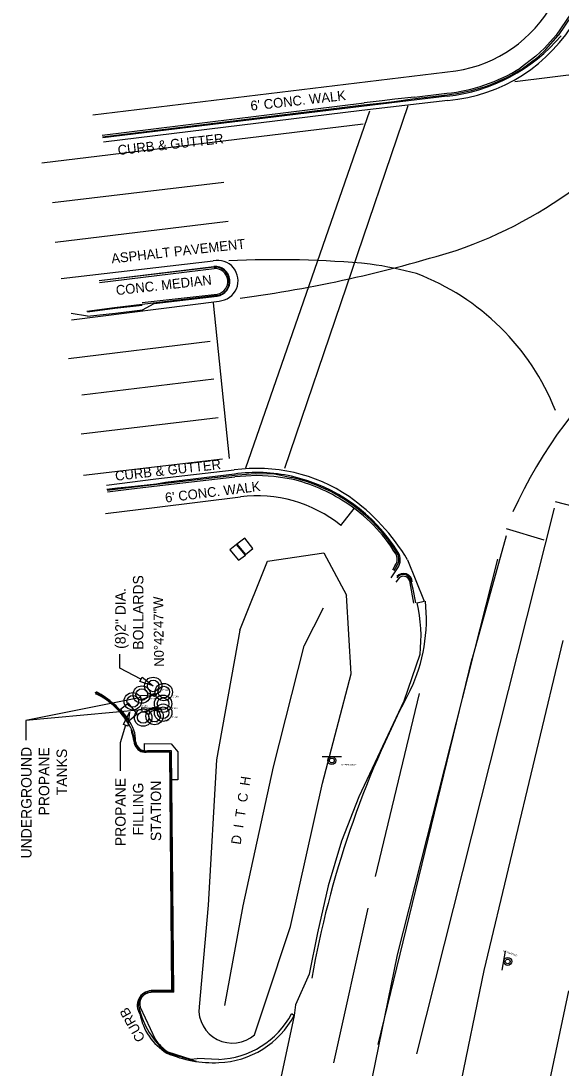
# Model space of a CAD drawing. Extents: x 925226 to 926411, y 852913 to 858733.
# Drawn here: x 925722 to 925877.3, y 857833.9 to 858134.9 of the extents above; entities that cross this region are included whole.
import ezdxf

# ---------------------------------------------------------------- set-up
doc = ezdxf.new("R2010")
doc.units = 0
for name, color, linetype in [('BankMent_ep', 7, 'Continuous'), ('CGep_ep', 7, 'Continuous'), ('CGFace_ep', 7, 'Continuous'), ('CLConst_dp', 7, 'Continuous'), ('ConcSlabs_ep', 7, 'Continuous'), ('CurbRamp_ep', 7, 'Continuous'), ('Ditch_ep', 7, 'Continuous'), ('EndTreat_ep', 7, 'Continuous'), ('LaneLine_ep', 7, 'Continuous'), ('ManholeSW_ep', 7, 'Continuous'), ('PavtAsphalt_ep', 7, 'Continuous'), ('PavtCrown_ep', 7, 'Continuous'), ('PavtMisc_ep', 7, 'Continuous'), ('Pump_ep', 7, 'Continuous'), ('SidewalkBack_ep', 7, 'Continuous'), ('TankUG_ep', 7, 'Continuous'), ('TextLabel', 7, 'Continuous'), ('TextNotes', 7, 'Continuous'), ('XSPt_ep', 7, 'Continuous')]:
    doc.layers.add(name, color=color, linetype=linetype)

# ---------------------------------------------------------------- blocks, each defined once
blk = doc.blocks.new('SSS')
at = {"layer": 'ManholeSW_ep'}
blk.add_line((-2.77, 1.15), (2.77, 1.15), dxfattribs=at)
for radius in [1.15, 0.692]:
    blk.add_circle((0, 0), radius, dxfattribs=at)
blk = doc.blocks.new('BOL')
at = {"layer": 'TextNotes'}
for radius in [2.5, 1.67]:
    blk.add_circle((0, 0), radius, dxfattribs=at)

msp = doc.modelspace()

# ---------------------------------------------------------------- linework, layer by layer
at = {"layer": 'BankMent_ep'}
msp.add_line((925879.41, 857856.06), (925859.54, 857762.3), dxfattribs=at)
at = {"layer": 'CGep_ep'}
for p, q in [((925844.57, 858113.33), (925819.92, 858110.33)), ((925819.92, 858110.33), (925745.52, 858101.32)), ((925748.99, 858052.26), (925741.1, 858051.24)), ((925756.9, 858053.15), (925748.99, 858052.26)), ((925760.95, 858001.88), (925763.57, 858002.32)), ((925763.57, 858002.32), (925783.36, 858004.67)), ((925746.74, 858000.34), (925749.79, 858000.73)), ((925749.79, 858000.73), (925752.93, 858001.01)), ((925752.93, 858001.01), (925760.95, 858001.88)), ((925828.42, 857974.82), (925830.35, 857977.68))]:
    msp.add_line(p, q, dxfattribs=at)
msp.add_arc((925839.52, 858162.39), 49.32, 275.8847, 319.9807, dxfattribs=at)
for centre, major_axis, ratio, start_param, end_param in [((925789.74, 857958.16), (5.87, -46.57), 0.999983, 2.79936, 3.152396), ((925789.14, 857956.76), (-18.57, -44.75), 0.999987, 2.514891, 3.312332), ((925827.04, 857979.96), (0.79, -3.94), 0.997503, 0.770936, 1.938401), ((925831.98, 857973.54), (-0.24, -2.54), 0.99836, 1.723789, 4.078539)]:
    msp.add_ellipse(centre, major_axis=major_axis, ratio=ratio, start_param=start_param, end_param=end_param, dxfattribs=at)
at = {"layer": 'CGFace_ep'}
for p, q in [((925880.51, 858136.71), (925876.45, 858130.76)), ((925834.59, 858112.51), (925844.5, 858113.71)), ((925745.43, 858101.64), (925820.52, 858110.81)), ((925777.48, 858064.14), (925744.52, 858060.23)), ((925778.48, 858055.96), (925756.9, 858053.41)), ((925748.88, 858052.42), (925740.96, 858051.4)), ((925756.9, 858053.41), (925748.88, 858052.42)), ((925763.54, 858002.01), (925784.24, 858004.38)), ((925746.84, 857999.99), (925752.96, 858000.75)), ((925752.96, 858000.75), (925763.54, 858002.01)), ((925830.01, 857978.15), (925829.21, 857976.86)), ((925834.75, 857971.52), (925834.11, 857974.13)), ((925835.55, 857967.58), (925834.75, 857971.52)), ((925764.94, 857924.72), (925758.33, 857924.77)), ((925765.63, 857856.07), (925764.94, 857924.72)), ((925759.41, 857855.97), (925765.63, 857856.07)), ((925764.01, 857838.27), (925772.37, 857835.86))]:
    msp.add_line(p, q, dxfattribs=at)
for centre, major_axis, ratio, start_param, end_param in [((925839.75, 858162.27), (47.08, -12.79), 0.999995, 5.075228, 5.540501), ((925777.77, 858060.02), (-4.14, -0.11), 0.998077, 1.714298, 4.755444), ((925789.06, 857956.6), (10.46, -47.15), 0.999974, 1.904479, 2.699589), ((925827.28, 857980.17), (-0.33, 3.39), 0.99614, 3.978822, 5.155955), ((925831.94, 857973.49), (1.22, -1.92), 0.991597, 1.29658, 3.544937), ((925734.57, 857922.71), (6.99, 19.88), 0.999748, 5.424017, 6.19158), ((925743.69, 857927.19), (-3.44, -10.43), 0.999738, 1.919623, 2.186463), ((925757.95, 857928.08), (3.31, -0.42), 0.999662, 3.437582, 4.951758), ((925759.49, 857852.27), (3.25, 1.78), 0.999868, 1.090636, 2.917068), ((925779.28, 857856.78), (15.79, -18.09), 0.999104, 4.226719, 4.875631)]:
    msp.add_ellipse(centre, major_axis=major_axis, ratio=ratio, start_param=start_param, end_param=end_param, dxfattribs=at)
at = {"layer": 'ConcSlabs_ep'}
for p, q in [((925784.01, 857984.35), (925782.06, 857982.85)), ((925786.53, 857981.37), (925784.01, 857984.35)), ((925786.41, 857986.2), (925784.03, 857984.49)), ((925784.03, 857984.49), (925786.57, 857981.49)), ((925788.64, 857983.23), (925786.41, 857986.2)), ((925782.06, 857982.85), (925784.56, 857979.86)), ((925784.56, 857979.86), (925786.53, 857981.37)), ((925786.57, 857981.49), (925788.64, 857983.23)), ((925757.47, 857927.2), (925757.43, 857925.08)), ((925757.47, 857927.2), (925765.19, 857927.08)), ((925765.19, 857927.08), (925767.12, 857924.82)), ((925767.12, 857924.82), (925767.08, 857916.69)), ((925767.08, 857916.69), (925765.38, 857916.73))]:
    msp.add_line(p, q, dxfattribs=at)
at = {"layer": 'CurbRamp_ep'}
for p, q in [((925875.92, 858130.82), (925872.51, 858127.09)), ((925872.95, 858126.68), (925876.45, 858130.76)), ((925872.51, 858127.09), (925870.05, 858124.81)), ((925870.63, 858124.52), (925872.95, 858126.68)), ((925870.05, 858124.81), (925865.54, 858121.38)), ((925865.78, 858121), (925870.63, 858124.52)), ((925820.52, 858110.81), (925826.01, 858111.39)), ((925825.84, 858112), (925820.67, 858111.35)), ((925829.5, 858112.43), (925825.84, 858112)), ((925826.01, 858111.39), (925829.3, 858111.72)), ((925829.3, 858111.72), (925834.59, 858112.51)), ((925835.18, 858113.03), (925829.5, 858112.43)), ((925789.82, 858004.19), (925783.52, 858003.82)), ((925784.24, 858004.38), (925789.48, 858004.83)), ((925789.48, 858004.83), (925794.91, 858004.71)), ((925794.75, 858003.98), (925789.82, 858004.19)), ((925799.75, 858003.2), (925794.75, 858003.98)), ((925794.91, 858004.71), (925799.78, 858003.7))]:
    msp.add_line(p, q, dxfattribs=at)
at = {"layer": 'Ditch_ep'}
for p, q in [((925792.92, 857979.63), (925809.04, 857981.97)), ((925809.04, 857981.97), (925815.6, 857969.8)), ((925784.94, 857959.72), (925792.92, 857979.63)), ((925816.92, 857947.18), (925815.6, 857969.8)), ((925803.41, 857955.25), (925808.97, 857966.18)), ((925784.94, 857959.72), (925778.2, 857922.52)), ((925794.64, 857920.45), (925803.41, 857955.25)), ((925808.67, 857915.73), (925816.92, 857947.18)), ((925778.2, 857922.52), (925775.84, 857880.67)), ((925785.86, 857880.51), (925794.64, 857920.45)), ((925799.52, 857874.53), (925808.67, 857915.73)), ((925775.84, 857880.67), (925773.21, 857851.51)), ((925780.67, 857851.9), (925785.86, 857880.51)), ((925792.2, 857852.6), (925799.52, 857874.53)), ((925789.15, 857843.46), (925792.2, 857852.6))]:
    msp.add_line(p, q, dxfattribs=at)
msp.add_ellipse((925782.78, 857850.66), major_axis=(-2.33, -9.33), ratio=0.999986, start_param=4.869605, end_param=7.251591, dxfattribs=at)
at = {"layer": 'EndTreat_ep'}
for p, q in [((926001.53, 858134.57), (925864.02, 858117.45)), ((925822.21, 858109.02), (925786.59, 858006.39)), ((925797.92, 858006.37), (925833.36, 858110.63)), ((925728.02, 858094.12), (925820.37, 858105.31)), ((925733.57, 858060.84), (925777.3, 858065.94)), ((925736.59, 858048.97), (925779, 858054.4)), ((925782.01, 858009.08), (925777.35, 858053.88)), ((925735.7, 858037.88), (925776.43, 858042.9)), ((925777.51, 858031.89), (925739.55, 858027.32)), ((925778.71, 858020.81), (925739.29, 858016.14)), ((925740.04, 858004.31), (925779.95, 858009.04)), ((925875.55, 857996.8), (925888.4, 857993.38)), ((925875.26, 857994.8), (925835.75, 857837.98)), ((925861.46, 857989.01), (925872.33, 857985.72)), ((925861.51, 857986.85), (925851.69, 857951.6)), ((925824.68, 857840.65), (925851.69, 857951.6)), ((925836.52, 857941.56), (925823.88, 857888.97)), ((925821.76, 857879.82), (925811.89, 857835.38))]:
    msp.add_line(p, q, dxfattribs=at)
for centre, major_axis, ratio, start_param, end_param in [((925807.98, 858185.37), (-64.65, -104.4), 0.999977, 0.878674, 1.553582), ((925735.62, 858426.35), (348.82, 136.69), 0.999242, 4.47159, 4.641363), ((925778.58, 858060.23), (-4.43, 3.83), 0.999929, 2.354299, 5.646891), ((925795.54, 857785.19), (-281.35, -14.6), 0.997761, 4.565072, 4.709651), ((925986.75, 857938.13), (-47.22, 126.76), 0.999982, 6.209163, 7.073626), ((925805.61, 857948.97), (94.25, -69.77), 0.999905, 1.947991, 2.064033), ((925811.17, 857997.43), (67.76, -14.77), 0.999977, 0.591396, 1.423059), ((925791.11, 857962.96), (31.61, -35.42), 0.999993, 0.396364, 0.951681), ((926084.23, 857810.7), (107.56, 262.01), 0.998689, 1.475772, 1.785976)]:
    msp.add_ellipse(centre, major_axis=major_axis, ratio=ratio, start_param=start_param, end_param=end_param, dxfattribs=at)
at = {"layer": 'LaneLine_ep'}
for p, q in [((925780.37, 858088.43), (925731.1, 858082.59)), ((925731.88, 858071.34), (925781.61, 858077.4))]:
    msp.add_line(p, q, dxfattribs=at)
at = {"layer": 'PavtAsphalt_ep'}
for p, q in [((925844.73, 858112.06), (925820, 858109.15)), ((925820, 858109.15), (925745.78, 858100.04)), ((925744.47, 858060.34), (925777.51, 858064.36)), ((925756.98, 858051.88), (925760.34, 858053.64)), ((925760.34, 858053.64), (925778.44, 858055.79)), ((925741.18, 858050.01), (925736.45, 858050.85)), ((925741.18, 858050.01), (925749.19, 858050.91)), ((925749.19, 858050.91), (925756.98, 858051.88)), ((925760.78, 858003.24), (925783.31, 858005.82)), ((925746.57, 858001.48), (925760.78, 858003.24)), ((925833.15, 857980.03), (925837.92, 857968.08)), ((925835.9, 857967.66), (925837.92, 857968.08)), ((925877.79, 857956.76), (925855.06, 857861.93)), ((925836.73, 857952.8), (925832.05, 857939.32)), ((925832.05, 857939.32), (925819.14, 857911.81)), ((925819.14, 857911.81), (925814.12, 857899.08)), ((925814.12, 857899.08), (925810.33, 857886.22)), ((925810.33, 857886.22), (925807.24, 857872.73)), ((925807.24, 857872.73), (925804.87, 857860.9)), ((925804.87, 857860.9), (925800.95, 857852.04)), ((925855.06, 857861.93), (925834.79, 857763.94)), ((925800.95, 857852.04), (925800.58, 857848.96)), ((925800.58, 857848.96), (925785.83, 857779.96))]:
    msp.add_line(p, q, dxfattribs=at)
for centre, major_axis, ratio, start_param, end_param in [((925840.63, 858159.33), (46.88, 7.33), 0.999985, 4.643805, 5.609384), ((925777.77, 858060.05), (-3.4, 2.67), 0.999377, 2.39093, 5.438202), ((925789.86, 857958.86), (13.96, -45.32), 0.999977, 2.250552, 2.981182), ((925781.21, 857948.82), (-44.99, -40.59), 0.999989, 2.94858, 3.360245), ((925793.57, 857957.84), (-4.64, 43.29), 0.998142, 4.489881, 4.833395)]:
    msp.add_ellipse(centre, major_axis=major_axis, ratio=ratio, start_param=start_param, end_param=end_param, dxfattribs=at)
at = {"layer": 'PavtCrown_ep'}
for p, q in [((925859.01, 857980.15), (925830.19, 857866.43)), ((925830.19, 857866.43), (925809.98, 857767.73))]:
    msp.add_line(p, q, dxfattribs=at)
at = {"layer": 'PavtMisc_ep'}
for p, q in [((925764.8, 857924.56), (925758.02, 857924.68)), ((925765.42, 857856.17), (925764.8, 857924.56)), ((925765.42, 857856.17), (925759.49, 857856.12))]:
    msp.add_line(p, q, dxfattribs=at)
for centre, major_axis, ratio, start_param, end_param in [((925733.99, 857921.6), (2.98, -21.85), 0.999501, 1.912317, 2.560267), ((925845.8, 857950.94), (61.1, -71.86), 0.99851, 4.213761, 4.268858), ((925757.74, 857927.87), (2.74, -1.68), 0.9938, 4.076968, 5.34781), ((925759.66, 857851.91), (4.13, -0.83), 0.999966, 1.81118, 3.951922), ((925772.57, 857852.38), (-11.25, 12.24), 0.998205, 1.002975, 1.852635), ((925778.04, 857860.99), (-19.75, -16.22), 0.999425, 0.916392, 1.963788), ((925777.25, 857868.34), (-32.64, -5.03), 0.997233, 1.003913, 1.467759)]:
    msp.add_ellipse(centre, major_axis=major_axis, ratio=ratio, start_param=start_param, end_param=end_param, dxfattribs=at)
at = {"layer": 'Pump_ep'}
msp.add_lwpolyline([(925753.13, 857933.82), (925755.46, 857935.71), (925752.94, 857938.82), (925750.61, 857936.93)], close=True, dxfattribs=at)
at = {"layer": 'SidewalkBack_ep'}
for p, q in [((925742.7, 858107.92), (925847.07, 858120.56)), ((925761.15, 857995.14), (925785.1, 857998.09)), ((925746.29, 857993.27), (925761.15, 857995.14)), ((925813.97, 857989.88), (925817.82, 857994.78))]:
    msp.add_line(p, q, dxfattribs=at)
for centre, major_axis, ratio, start_param, end_param in [((925841.12, 858158.75), (36.57, -12.52), 0.999994, 5.196605, 6.108925), ((925789.87, 857959.99), (2.01, -38.34), 0.999985, 2.410612, 3.213854)]:
    msp.add_ellipse(centre, major_axis=major_axis, ratio=ratio, start_param=start_param, end_param=end_param, dxfattribs=at)
at = {"layer": 'TankUG_ep'}
for centre in [(925760.42, 857941.15), (925760.78, 857937.22)]:
    msp.add_circle(centre, 0.46, dxfattribs=at)
at = {"layer": 'TextLabel'}
for points in [[(925750.45, 857948.88), (925750.45, 857952.87)], [(925756.51, 857945.64), (925750.45, 857948.88)], [(925756.49, 857940.38), (925723.46, 857933.83)], [(925756.8, 857936.86), (925723.46, 857933.83)], [(925723.46, 857933.83), (925723.46, 857928.18)], [(925752.08, 857932.41), (925750.52, 857927.35)], [(925750.52, 857927.35), (925750.52, 857919.35)]]:
    msp.add_lwpolyline(points, dxfattribs=at)
for points in [[(925756.82, 857946.23), (925760.03, 857943.75), (925756.19, 857945.05)], [(925756.36, 857941.03), (925760.42, 857941.15), (925756.62, 857939.72)], [(925751.45, 857932.6), (925753.26, 857936.23), (925752.72, 857932.21)], [(925756.74, 857937.53), (925760.78, 857937.22), (925756.86, 857936.2)]]:
    msp.add_lwpolyline(points, close=True, dxfattribs=at)
at = {"layer": 'XSPt_ep'}
for p, q in [((925880.04, 858136.89), (925875.92, 858130.82)), ((925835.18, 858113.03), (925844.41, 858114.14)), ((925745.36, 858102.07), (925820.67, 858111.35)), ((925744.59, 858059.75), (925777.53, 858063.74)), ((925756.83, 858053.94), (925778.47, 858056.41)), ((925763.6, 858001.54), (925783.52, 858003.82)), ((925746.89, 857999.53), (925753.01, 858000.26)), ((925753.01, 858000.26), (925763.6, 858001.54)), ((925829.64, 857978.49), (925828.79, 857977.06)), ((925830.8, 857974.89), (925829.79, 857973.59)), ((925834.95, 857967.49), (925833.88, 857973.41)), ((925765.31, 857925.1), (925758.37, 857925.04)), ((925765.94, 857855.73), (925765.31, 857925.1)), ((925765.94, 857855.73), (925759.41, 857855.63)), ((925756.26, 857851.38), (925760.63, 857842.14)), ((925800.58, 857848.96), (925799.83, 857849.47)), ((925764.21, 857838.56), (925770.85, 857836.41)), ((925770.85, 857836.41), (925772.68, 857836.57)), ((925778.87, 857836.37), (925772.68, 857836.57))]:
    msp.add_line(p, q, dxfattribs=at)
for centre, major_axis, ratio, start_param, end_param in [((925839.71, 858162.28), (40.43, -26.56), 0.999997, 5.391095, 5.856977), ((925777.77, 858060.04), (-3.65, -0.66), 0.997872, 1.580891, 4.596561), ((925788.05, 857954.51), (22.45, -44.77), 0.999969, 2.103853, 2.441031), ((925790.21, 857957.63), (-46.19, -2.94), 0.999982, 3.624485, 4.078496), ((925827.37, 857980.17), (-2.23, 1.73), 0.999411, 3.165183, 4.36923), ((925831.94, 857973.31), (0.39, -1.91), 0.995939, 1.422418, 3.565498), ((925730.92, 857918.3), (-8.94, 25.46), 0.999069, 4.99165, 5.451876), ((925745.63, 857928.03), (-8.64, 3.59), 0.999824, 3.504431, 4.215651), ((925758.02, 857928.09), (0.25, 3.05), 0.999852, 1.768601, 3.337477), ((925759.52, 857852.26), (2.54, 2.22), 0.999812, 0.886224, 2.688141), ((925777.98, 857861.1), (-18.74, -16.18), 0.999592, 0.89473, 1.939864), ((925771.29, 857849.22), (8.55, -9.57), 0.996718, 4.570122, 4.967006)]:
    msp.add_ellipse(centre, major_axis=major_axis, ratio=ratio, start_param=start_param, end_param=end_param, dxfattribs=at)

# ---------------------------------------------------------------- block references
at = {"layer": 'ManholeSW_ep'}
msp.add_blockref('SSS', (925811.38, 857922.29), dxfattribs=at)
at = {"layer": 'ManholeSW_ep', "rotation": 79.79060634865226}
msp.add_blockref('SSS', (925861.95, 857864.53), dxfattribs=at)
at = {"layer": 'TextNotes'}
for p in [(925760.03, 857943.75), (925756.75, 857941.26), (925763.08, 857941.97), (925754.17, 857939.31), (925762.87, 857938.62), (925757.15, 857934.65), (925760.43, 857935.07), (925762.9, 857936.04)]:
    msp.add_blockref('BOL', p, dxfattribs=at)

# ---------------------------------------------------------------- texts
at = {"layer": 'CLConst_dp'}
for s, p in [('2"DIA', (925762.53, 857942.23)), ('2"DIA', (925759.25, 857939.74)), ('2"DIA', (925765.58, 857940.45)), ('2"DIA', (925756.67, 857937.79)), ('2"DIA', (925765.37, 857937.1)), ('2"DIA', (925759.65, 857933.14)), ('2"DIA', (925762.93, 857933.56)), ('2"DIA', (925765.4, 857934.52)), ('SPEED LIMIT', (925814.15, 857920.77))]:
    msp.add_text(s, height=0.5, dxfattribs=at).set_placement(p)
msp.add_text('NO PARKING', height=0.5, rotation=339.5812, dxfattribs=at).set_placement((925860.55, 857867.4))
at = {"layer": 'TextLabel'}
for s, height, rotation, p in [("6' CONC. WALK", 2.8, 6.4219, (925788.16, 858109.11)), ('CURB & GUTTER', 2.8, 6.4219, (925749.99, 858096.36)), ('ASPHALT PAVEMENT', 2.8, 6.4219, (925748.14, 858065.19)), ('CONC. MEDIAN', 2.8, 6.4219, (925749.47, 858056.07)), ('CURB & GUTTER', 2.8, 6.4219, (925749.25, 858002.69)), ("6' CONC. WALK", 2.8, 7.0152, (925763.62, 857996.44)), ('BOLLARDS', 3, 90, (925757.21, 857954.16)), ('(8)2" DIA.', 3, 90, (925752.11, 857954.39)), ('N0°42\'47"W', 2.8, 90.713, (925763.12, 857949.26)), ('UNDERGROUND', 3, 90, (925725.06, 857894.12)), ('PROPANE', 3, 90, (925730.15, 857906.49)), ('TANKS', 3, 90, (925735.25, 857912.29)), ('PROPANE', 3, 90, (925752.11, 857897.66)), ('FILLING', 3, 90, (925757.21, 857900.77)), ('STATION', 3, 90, (925762.31, 857899.11)), ('D  I  T  C  H', 2.8, 81.4783, (925785.16, 857897.99)), ('CURB', 2.8, 119.3728, (925757.84, 857842.35))]:
    msp.add_text(s, height=height, rotation=rotation, dxfattribs=at).set_placement(p)

doc.saveas('drawing.dxf')
